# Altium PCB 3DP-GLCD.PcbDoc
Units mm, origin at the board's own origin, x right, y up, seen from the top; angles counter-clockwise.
Board outline 95 x 47 mm, 2 copper layers (Top Layer, Bottom Layer); 16 components, 32 nets, 122 pads, 0 vias.
Unrouted connection lines stored in the file: 1.
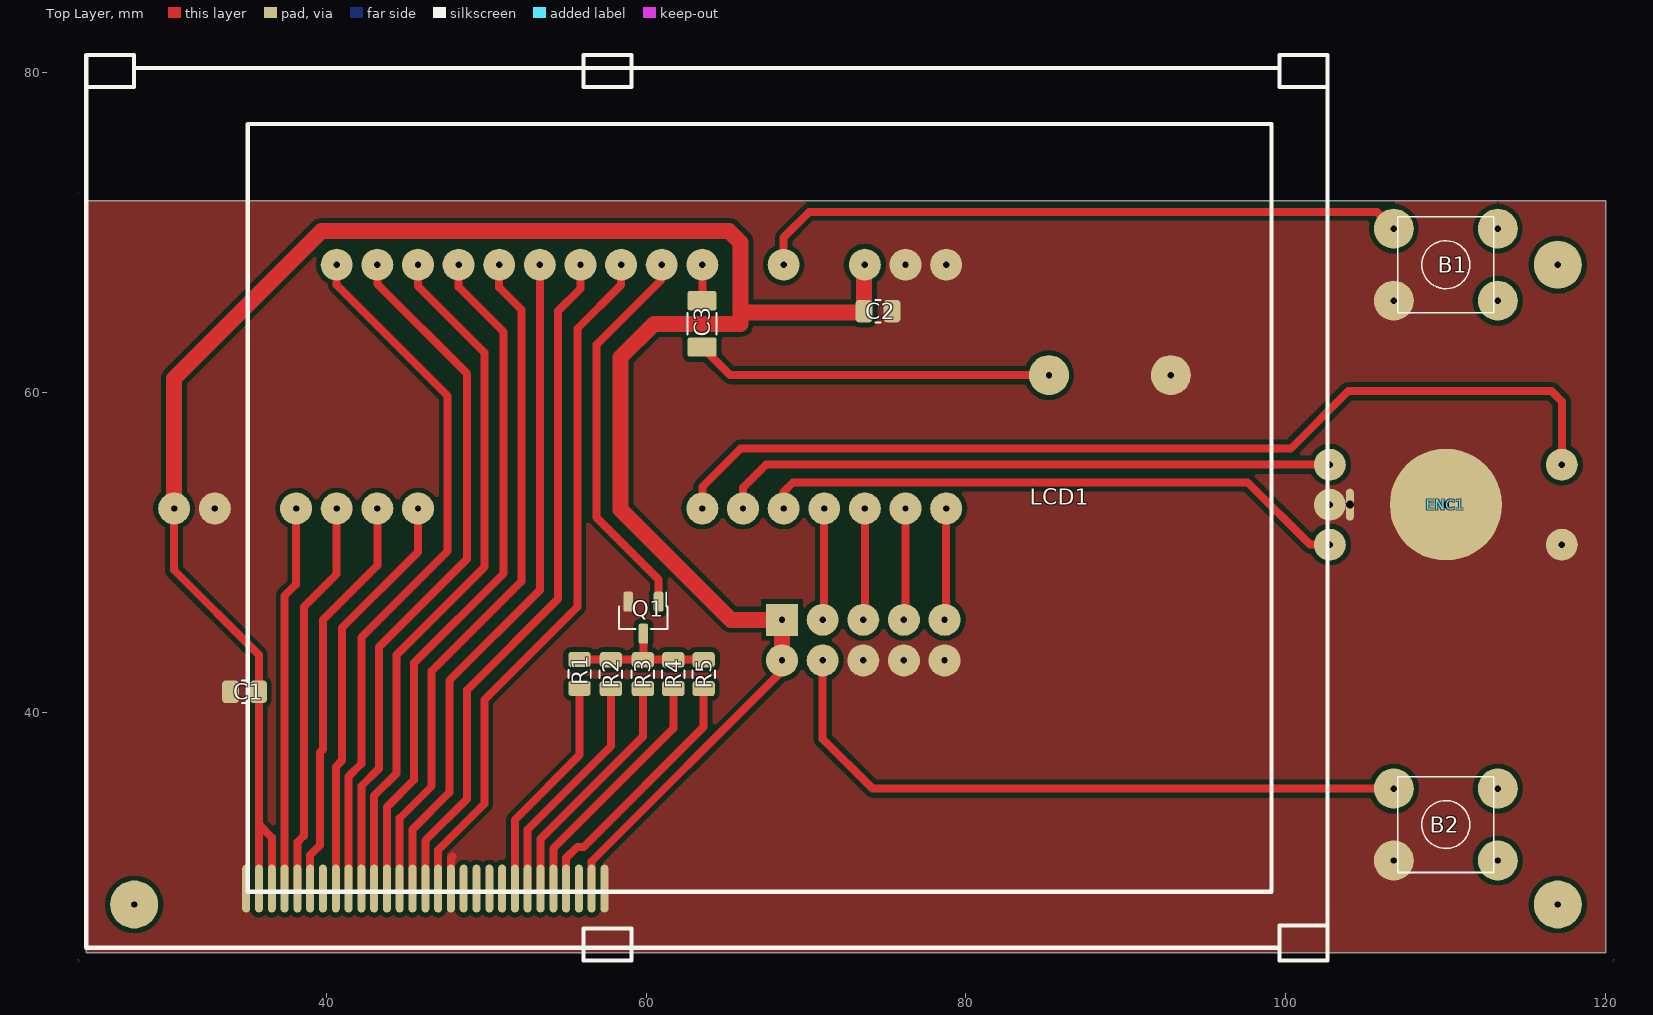
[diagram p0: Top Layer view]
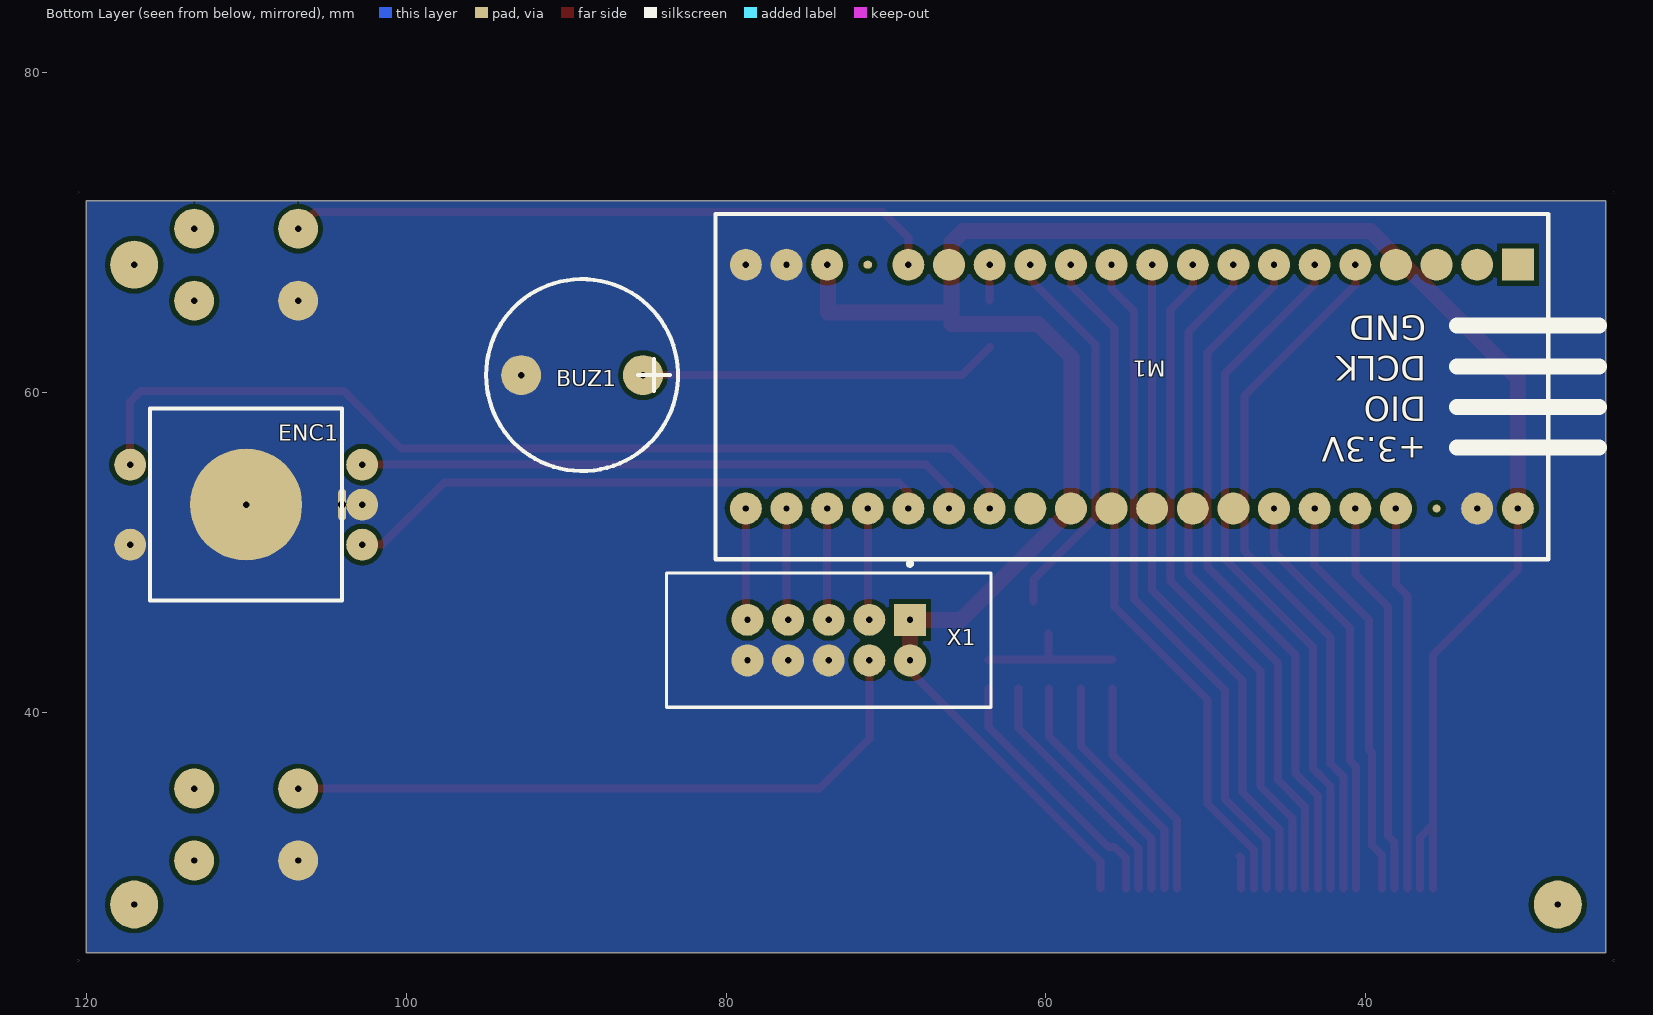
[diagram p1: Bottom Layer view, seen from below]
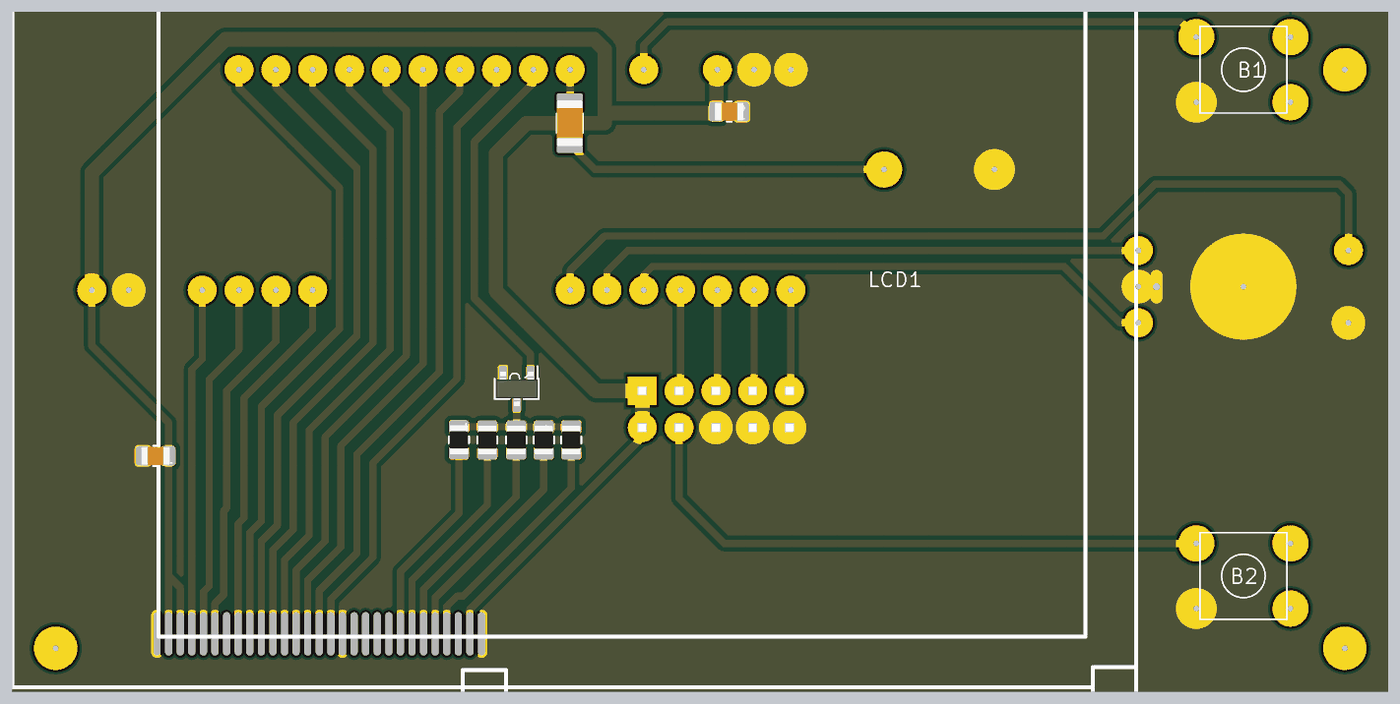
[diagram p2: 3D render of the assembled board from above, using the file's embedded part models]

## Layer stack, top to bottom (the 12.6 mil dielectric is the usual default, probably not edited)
Top Layer: signal copper 0.0356
Dielectric: dielectric 0.32, FR-4, Dk 4.8
Bottom Layer: signal copper 0.0356

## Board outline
25,25 120,25 120,72 25,72

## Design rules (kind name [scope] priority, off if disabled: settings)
Clearance Clearance_1 [InPolygon] p1: gap=0.3
Clearance [All] p2: gap=0.2
ComponentClearance [All] p1 off: gap=0.254 collisioncheckmode=3 verticalgap=0.254 showdistances=FALSE
FabricationTestPointUsage [All] p1 off: valid=0 allowmultiple=FALSE
FabricationTestpoint [All] p1 off: side=3 testpointundercomponent=TRUE minsize=1.016 maxsize=2.54 preferedsize=1.524 minholesize=0 maxholesize=1.016 preferedholesize=0.813 testpointgrid=0.025 allowsidetop=TRUE allowsidebottom=TRUE usegrid=TRUE gridtolerance=0
FanoutControl Fanout_BGA [IsBGA] p1 off: bgadir=Out bgaviamode=Centered fanoutstyle=Auto fanoutdirection=Alternating viagrid=0.025 // Fanout_BGA (Default Rule)
FanoutControl Fanout_LCC [IsLCC] p2 off: bgadir=Out bgaviamode=Centered fanoutstyle=Auto fanoutdirection=Alternating viagrid=0.025 // Fanout_LCC (Default Rule)
FanoutControl Fanout_SOIC [IsSOIC] p3 off: bgadir=Out bgaviamode=Centered fanoutstyle=Auto fanoutdirection=Alternating viagrid=0.025 // Fanout_SOIC (Default Rule)
FanoutControl Fanout_Small [(CompPinCount < 5)] p4 off: bgadir=Out bgaviamode=Centered fanoutstyle=Auto fanoutdirection=OutThenIn viagrid=0.025 // Fanout_Small (Default Rule)
FanoutControl Fanout_Default [All] p5 off: bgadir=Out bgaviamode=Centered fanoutstyle=Auto fanoutdirection=Alternating viagrid=0.025 // Fanout_Default (Default Rule)
PolygonConnect [All] p1: connectstyle=Relief reliefconductorwidth=0.5 reliefentries=4 polygonreliefangle="90 Angle" airgapwidth=-0.1
RoomDefinition 3DP-GLCD [InComponentClass('3DP-GLCD')] p1: confinementstyle=ConfineOut formatcopy=TRUE lockcomponents=FALSE outline 27.3,82.1 53.9,82.1 53.9,86.3 27.3,86.3
RoutingVias [All] p1: holewidth=0.711 width=1.27 viastyle="Through Hole" minholewidth=0.711 minwidth=1.27 maxholewidth=0.711 maxwidth=1.27
SilkToSilkClearance [All] p1 off: silktosilkclearance=0.254
SilkscreenOverComponentPads [All] p1 off: minsilkscreentomaskgap=0.254
SolderMaskExpansion [All] p1: expansion=0.16
Width [All] p1: maxlimit=2 minlimit=0.2 preferedwidth=0.3
18 further rules are at their usual default settings.

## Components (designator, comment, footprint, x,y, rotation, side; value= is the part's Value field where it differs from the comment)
B1 "SWT-2-x" SWT-2-x 110,68 r0 top
B2 "SWT-2-x" SWT-2-x 110,33 r0 top
BUZ1 "Buzer" Buzer_12xx 89,61.1 r0 bottom
C1 "Cap" C0805_Murata 34.9,41.3 r180 top
C2 "Cap" C0805_Murata 74.5,65.1 r0 top
C3 "Cap" C1206_Murata 63.5,64.3 r270 top
ENC1 "Encoder" Encoder_bot 110,53 r0 top
LCD1 "ILI9325" LCD-ILI9325-29pin-top 35,29 r0 top locked
M1 "Arduino-STM32" ARDUINO-STM32 30.5,68 r0 bottom
Q1 "IRLML6344" SOT23-3_IR 59.83,45.933 r270 top
R1 "R" R0805_UniOhm 55.84,42.415 r90 top
R2 "R" R0805_UniOhm 57.8,42.4 r90 top
R3 "R" R0805_UniOhm 59.8,42.4 r90 top
R4 "R" R0805_UniOhm 61.7,42.4 r90 top
R5 "R" R0805_UniOhm 63.6,42.4 r90 top
X1 "BH-10" BH-10 68.5,45.8 r0 bottom

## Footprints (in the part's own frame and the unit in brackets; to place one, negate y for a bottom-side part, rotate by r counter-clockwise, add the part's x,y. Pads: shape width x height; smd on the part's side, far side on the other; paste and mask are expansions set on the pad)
ARDUINO-STM32 [mm]
  rect 2x2 smd: 1(0,0)
  round 2 smd: 2(2.54,0) 3(5.08,0) 4(7.62,0) 15(35.56,0) 28(30.48,15.24) 29(27.94,15.24) 30(25.4,15.24) 31(22.86,15.24) 32(20.32,15.24) 33(17.78,15.24)
  round 2 hole 0.4: 5(10.16,0) 6(12.7,0) 7(15.24,0) 8(17.78,0) 9(20.32,0) 10(22.86,0) 11(25.4,0) 12(27.94,0) 13(30.48,0) 14(33.02,0) 16(38.1,0) 18(43.18,0) 19(45.72,0) 20(48.26,0) 21(48.26,15.24) 22(45.72,15.24) 23(43.18,15.24) 24(40.64,15.24) 25(38.1,15.24) 26(35.56,15.24) 27(33.02,15.24) 34(15.24,15.24) 35(12.7,15.24) 36(10.16,15.24) 37(7.62,15.24) 39(2.54,15.24) 40(0,15.24)
  oval 0.54x0.5 smd: 17(40.64,0)
  round 0.5 smd: 38(5.08,15.24)
  silkscreen extent -5.08,-3.17 50.17,18.41
BH-10 [mm] "Shrouded Header,vertical,2.54mm pitch;1.00mm lead width,10 pins,2 rows,5 pins per row,20.30mm L X 8.40mm W X 9.30mm H body"
  rect 2x2 hole 0.4: 1(0,0)
  round 2 hole 0.4: 2(0,2.54) 3(2.54,0) 4(2.54,2.54) 5(5.08,0) 6(5.08,2.54) 7(7.62,0) 8(7.62,2.54) 9(10.16,0) 10(10.16,2.54)
  silkscreen extent -5.07,-3.63 15.23,5.47, body extent -5.07,-3.13 15.23,5.97, height 9.3
Buzer_12xx [mm]
  round 2.5 hole 0.4: 1(-3.81,0) 2(3.81,0)
  silkscreen extent -6,-6 6,6
C0805_Murata [mm] "Capacitor, Chip; 2.00 mm L X 1.25 mm W X 1.40 mm H body"
  rrect40% 1.05x1.4 smd paste-0.025 mask+0.05: 1(-0.875,0) 2(0.875,0)
  silkscreen extent -0.17,-0.7 0.17,0.7, body extent -1,-0.63 1,0.63, height 1.4
C1206_Murata [mm] "Capacitor, Chip; 3.20 mm L X 1.60 mm W X 1.80 mm H body"
  rrect20% 1.2x1.8 smd: 1(-1.45,0) 2(1.45,0)
  silkscreen extent -0.67,-0.9 0.67,0.9, body extent -1.6,-0.9 1.6,0.9, height 1.6
Encoder_bot [mm]
  oval 0.5x2 hole 0.5: 0(-6,0)
  round 7 hole 0.4: 0(0,0)
  round 2 hole 0.4: 1(-7.25,2.5) 2(-7.25,0) 3(-7.25,-2.5) 4(7.25,2.5) 5(7.25,-2.5)
LCD-ILI9325-29pin-top [mm]
  oval 0.5x3 smd: 1(0,0) 2(0.8,0) 3(1.6,0) 4(2.4,0) 5(3.2,0) 6(4,0) 7(4.8,0) 8(5.6,0) 9(6.4,0) 10(7.2,0) 11(8,0) 12(8.8,0) 13(9.6,0) 14(10.4,0) 15(11.2,0) 16(12,0) 17(12.8,0) 18(13.6,0) 19(14.4,0) 20(15.2,0) 21(16,0) 22(16.8,0) 23(17.6,0) 24(18.4,0) 25(19.2,0) 26(20,0) 27(20.8,0) 28(21.6,0) 29(22.4,0)
  silkscreen extent -10,-4.5 67.6,52.1
R0805_UniOhm [mm] "Resistor, Chip; 2.00 mm L X 1.275 mm W X 0.65 mm H body"
  rrect40% 0.95x1.4 smd paste-0.025 mask+0.05: 1(-0.9,0) 2(0.9,0)
  silkscreen extent -0.25,-0.7 0.25,0.7, body extent -1,-0.64 1,0.64, height 0.65
SOT23-3_IR [mm] "Small Outline Transistor (SOT23), 0.95 mm pitch; 3 pin, 2.92 mm L X 1.30 mm W X 1.12 mm H body"
  rrect40% 1.25x0.6 smd paste-0.025 mask+0.05: 1(-1,0.95) 2(-1,-0.95) 3(1,0)
  silkscreen extent -1.57,-1.52 0.7,1.52, body extent -1.18,-1.46 1.18,1.46, height 1.12
SWT-2-x [mm] "Button"
  round 2.5 hole 0.4: 1(-3.25,2.25) 2(-3.25,-2.25) 3(3.25,-2.25) 4(3.25,2.25)
  silkscreen extent -3,-3 3,3

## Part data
C1 C2: library part GRM21BR71H104KA01L
C3: library part GRM31CR71H475KA12L
ENC1: "Rotary Encoder with button"
LCD1: library part LCD-ILI9325-29pin, "TFT LCD"
M1: library part ARDUINO-STM32
Q1: library part IRLML6344TRPBF, "30 V, 5.0 A, 0.029 Ohm Single N-Channel HEXFET Power MOSFET"
R1 R2 R3 R4 R5: library part 0805S8F4700T50
X1: library part BH-10_2

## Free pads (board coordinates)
  round 0.13 hole 0.13: 0(24.5,24.5) 0(24.5,72.5) 0(120.5,24.5) 0(120.5,72.5)
  round 3 hole 0.4: 1(28,28) 1(117,28) 2(117,68)

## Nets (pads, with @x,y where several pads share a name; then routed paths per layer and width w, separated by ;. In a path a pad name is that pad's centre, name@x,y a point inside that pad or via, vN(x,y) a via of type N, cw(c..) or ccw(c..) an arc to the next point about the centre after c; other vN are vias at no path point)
+3.3V: C1.1 C2.1 LCD1.2 LCD1.3 LCD1.7 LCD1.28 M1.18 M1.40 X1.1 X1.2 | length 146.3
  Top Layer w0.5: M1.40 30.5,48.9 35.8,43.6 35.8,33 ; LCD1.2 35.8,33 ; LCD1.3 36.6,32.2 35.8,33 ; LCD1.28 56.6,30.7 68.5,42.6 X1.2
  Top Layer w1: M1.40 30.5,60.9 39.7,70.1 65.2,70.1 65.9,69.4 65.9,64.3 60.5,64.3 58.4,62.2 58.4,52.7 65.3,45.8 X1.1 X1.2 ; 65.9,65 73.625,65 M1.18@73.625,67.945
BEEP: C3.1 M1.14 | length 2.2
  Top Layer w0.5: C3.1@63.52,65.77 M1.14
CONTRAST: M1.13 Q1.1 | length 24.4
  Top Layer w0.5: Q1.1 60.78,48.32 56.9,52.2 56.9,63 60.98,67.08 M1.13
CS-: LCD1.4 M1.37 | length 24.1
  Top Layer w0.5: LCD1.4 37.4,47.3 38.12,48.02 M1.37
CS_2: M1.21 X1.9 | length 6.9
  Top Layer w0.5: X1.9@78.76,45.9 M1.21
D10: LCD1.9 M1.5 | length 44.4
  Top Layer w0.5: M1.5 40.66,66.74 47.6,59.8 47.6,50.1 42.2,44.7 42.2,36.8 41.4,36 LCD1.9
D11: LCD1.10 M1.6 | length 44.1
  Top Layer w0.5: LCD1.10 42.2,35.4 43.3,36.5 43.3,44.1 48.8,49.6 48.8,61.2 43.2,66.8 M1.6
D12: LCD1.11 M1.7 | length 43.6
  Top Layer w0.5: LCD1.11 43,34.8 44.4,36.2 44.4,43.6 49.9,49.1 49.9,62.5 45.74,66.66 M1.7
D13: LCD1.12 M1.8 | length 43.2
  Top Layer w0.5: LCD1.12 43.8,34.1 45.5,35.8 45.5,43.1 51.1,48.7 51.1,63.8 48.28,66.62 M1.8
D14: LCD1.13 M1.9 | length 42.7
  Top Layer w0.5: LCD1.13 44.6,33.4 46.6,35.4 46.6,42.6 52.2,48.2 52.2,65.2 50.82,66.58 M1.9
D15: LCD1.14 M1.10 | length 42.3
  Top Layer w0.5: LCD1.14 45.4,32.7 47.7,35 47.7,42 53.36,47.66 M1.10
D16: LCD1.15 M1.11 | length 43
  Top Layer w0.5: LCD1.15 46.2,32 48.8,34.6 48.8,41.4 54.5,47.1 54.5,65.1 55.9,66.5 M1.11
D17: LCD1.16 M1.12 | length 43.7
  Top Layer w0.5: LCD1.16 47,31.4 49.9,34.3 49.9,40.8 55.7,46.6 55.7,64 58.44,66.74 M1.12
GND: B1.2 B2.2 BUZ1.2 C1.2 C2.2 ENC1.0 ENC1.2 ENC1.5 LCD1.1 LCD1.17 LCD1.29 M1.19 M1.20 M1.39 Q1.2 X1.6 X1.8 X1.10 | length 2
  Top Layer w0.5: LCD1.17 47.8,30.9 47.9,31
KILL: B2.1 X1.4 | length 41.9
  Top Layer w0.5: X1.4 71.04,38.36 74.15,35.25 B2.1
MISO_2: M1.23 X1.5 | length 6.9
  Top Layer w0.5: X1.5@73.68,45.9 M1.23
MOSI_2: M1.24 X1.3 | length 6.9
  Top Layer w0.5: X1.3@71.14,45.9 M1.24
NetB1_1: B1.1 M1.16 | length 40.9
  Top Layer w0.5: M1.16 68.6,69.7 70.2,71.3 105.7,71.3 B1.1
NetBUZ1_1: BUZ1.1 C3.2 | length 22.4
  Top Layer w0.5: C3.2 65.25,61.1 BUZ1.1
NetENC1_1: ENC1.1 M1.26 | length 38.6
  Top Layer w0.5: M1.26 66.06,54.06 67.5,55.5 ENC1.1
NetENC1_3: ENC1.3 M1.25 | length 37.1
  Top Layer w0.5: M1.25 68.6,53.8 69.2,54.4 97.6,54.4 101.5,50.5 ENC1.3
NetENC1_4: ENC1.4 M1.27 | length 61.8
  Top Layer w0.5: M1.27 63.52,54.12 65.9,56.5 100.3,56.5 103.9,60.1 116.6,60.1 117.25,59.45 ENC1.4
NetLCD1_22: LCD1.22 R1.1 | length 14.2
  Top Layer w0.5: LCD1.22 51.8,33.3 55.84,37.34 R1.1
NetLCD1_23: LCD1.23 R2.1 | length 14.7
  Top Layer w0.5: LCD1.23 52.6,32.7 57.8,37.9 R2.1
NetLCD1_24: LCD1.24 R3.1 | length 15.2
  Top Layer w0.5: LCD1.24 53.4,32.1 59.8,38.5 R3.1
NetLCD1_25: LCD1.25 R4.1 | length 15.6
  Top Layer w0.5: LCD1.25 54.2,31.5 61.7,39 R4.1
NetLCD1_26: LCD1.26 R5.1 | length 16.3
  Top Layer w0.5: LCD1.26 55,30.9 55.7,31.6 56.1,31.6 63.6,39.1 R5.1
NetQ1_3: Q1.3 R1.2 R2.2 R3.2 R4.2 R5.2 | length 9.4
  Top Layer w0.5: R1.2 63.585,43.315 R5.2 ; R3.2@59.83,43.3 Q1.3
RS-: LCD1.5 M1.36 | length 24.8
  Top Layer w0.5: LCD1.5 38.2,31.9 38.6,32.3 38.6,46.6 40.66,48.66 M1.36
RST-: LCD1.8 M1.34 | length 25.9
  Top Layer w0.5: LCD1.8 40.6,36.6 41,37 41,45.3 45.74,50.04 M1.34
SCK_2: M1.22 X1.7 | length 6.9
  Top Layer w0.5: X1.7@76.22,45.9 M1.22
WR-: LCD1.6 M1.35 | length 25.5
  Top Layer w0.5: LCD1.6 39,31.1 39.6,31.7 39.6,37.5 39.8,37.7 39.8,45.8 43.2,49.2 M1.35
pads on no net: B1.3 B1.4 B2.3 B2.4 LCD1.18 LCD1.19 LCD1.20 LCD1.21 LCD1.27 M1.1 M1.2 M1.3 M1.4 M1.15 M1.17 M1.28 M1.29 M1.30 M1.31 M1.32 M1.33 M1.38

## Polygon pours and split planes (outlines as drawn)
GND on Top Layer "Bottom Layer-No Net" (solid, remove dead copper, pour order 6): 25,25 25,72 120,72 120,25
GND on Bottom Layer "Bottom Layer-No Net" (solid, remove dead copper, pour order 4): 25,25 25,72 120,72 120,25 25,25

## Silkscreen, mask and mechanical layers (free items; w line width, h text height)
OutBoard:
  the board outline again, w0.254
